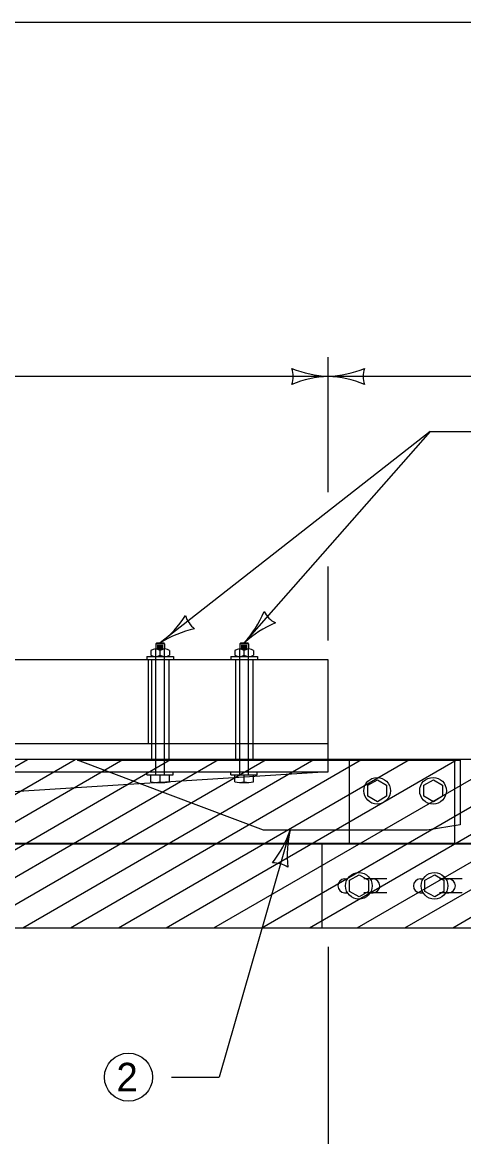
# Model space of a CAD drawing. Extents: x 49983 to 50021, y 49963.5 to 50011.4.
# Drawn here: x 50004.438 to 50005.363, y 49996.667 to 49998.999 of the extents above; entities that cross this region are included whole.
import ezdxf

# ---------------------------------------------------------------- set-up
doc = ezdxf.new("R2010")
doc.units = 0
for name, color, linetype in [('Level 1', 7, 'Continuous'), ('Level 10', 7, 'Continuous'), ('Level 2', 7, 'Continuous'), ('Level 3', 7, 'Continuous'), ('Level 4', 7, 'Continuous')]:
    doc.layers.add(name, color=color, linetype=linetype)

msp = doc.modelspace()

# ---------------------------------------------------------------- linework, layer by layer
at = {"layer": 'Level 1'}
for p, q in [((50004.7181, 49997.6984), (50004.7199, 49997.7002)), ((50004.7181, 49997.6984), (50004.7181, 49997.6876)), ((50004.7363, 49997.6984), (50004.7181, 49997.6984)), ((50004.7199, 49997.7002), (50004.7345, 49997.7002)), ((50004.7207, 49997.6956), (50004.7336, 49997.6956)), ((50004.7363, 49997.6984), (50004.7345, 49997.7002)), ((50004.7363, 49997.6984), (50004.7363, 49997.6876)), ((50004.8939, 49997.6984), (50004.8957, 49997.7002)), ((50004.8939, 49997.6984), (50004.8939, 49997.6876)), ((50004.9122, 49997.6984), (50004.8939, 49997.6984)), ((50004.8957, 49997.7002), (50004.9104, 49997.7002)), ((50004.8966, 49997.6956), (50004.9094, 49997.6956)), ((50004.9122, 49997.6984), (50004.9104, 49997.7002)), ((50004.9122, 49997.6984), (50004.9122, 49997.6876)), ((50004.6991, 49997.6717), (50004.7549, 49997.6717)), ((50004.6991, 49997.6717), (50004.6991, 49997.6651)), ((50004.7075, 49997.6846), (50004.7075, 49997.6747)), ((50004.7174, 49997.6876), (50004.737, 49997.6876)), ((50004.7207, 49997.6938), (50004.7336, 49997.6938)), ((50004.7207, 49997.692), (50004.7336, 49997.692)), ((50004.7207, 49997.6901), (50004.7336, 49997.6901)), ((50004.7272, 49997.6747), (50004.7272, 49997.6846)), ((50004.7469, 49997.6846), (50004.7469, 49997.6747)), ((50004.7549, 49997.6717), (50004.7549, 49997.6651)), ((50004.8749, 49997.6717), (50004.9308, 49997.6717)), ((50004.8749, 49997.6717), (50004.8749, 49997.6651)), ((50004.8834, 49997.6846), (50004.8834, 49997.6747)), ((50004.8932, 49997.6876), (50004.9129, 49997.6876)), ((50004.8966, 49997.6938), (50004.9094, 49997.6938)), ((50004.8966, 49997.692), (50004.9094, 49997.692)), ((50004.8966, 49997.6901), (50004.9094, 49997.6901)), ((50004.9031, 49997.6747), (50004.9031, 49997.6846)), ((50004.9227, 49997.6846), (50004.9227, 49997.6747)), ((50004.9308, 49997.6717), (50004.9308, 49997.6651)), ((50005.0789, 49997.6651), (50000.7665, 49997.6651)), ((50004.7024, 49997.4894), (50004.7024, 49997.6651)), ((50005.0789, 49997.456), (50005.0789, 49997.6651)), ((50005.0789, 49997.4894), (50002.1382, 49997.4894)), ((50006.3204, 49997.456), (50003.275, 49997.456)), ((50003.8396, 49997.1042), (50004.4489, 49997.456)), ((50003.9396, 49997.1042), (50004.5489, 49997.456)), ((50004.0396, 49997.1042), (50004.6489, 49997.456)), ((50004.1396, 49997.1042), (50004.7489, 49997.456)), ((50004.2396, 49997.1042), (50004.8489, 49997.456)), ((50004.3396, 49997.1042), (50004.9489, 49997.456)), ((50004.4396, 49997.1042), (50005.0489, 49997.456)), ((50004.5396, 49997.1042), (50005.1489, 49997.456)), ((50004.6396, 49997.1042), (50005.2489, 49997.456)), ((50004.7396, 49997.1042), (50005.3489, 49997.456)), ((50004.8396, 49997.1042), (50005.4489, 49997.456)), ((50004.9396, 49997.1042), (50005.5489, 49997.456)), ((50005.0396, 49997.1042), (50005.6489, 49997.456)), ((50009.122, 49997.456), (50005.1235, 49997.456)), ((50005.1396, 49997.1042), (50005.7489, 49997.456)), ((50005.2396, 49997.1042), (50005.8489, 49997.456)), ((50005.3396, 49997.1042), (50005.9489, 49997.456)), ((50003.2457, 49997.2799), (50005.4468, 49997.2799)), ((50006.3204, 49997.2803), (50003.275, 49997.2803)), ((50009.1498, 49997.2803), (50005.1235, 49997.2803)), ((50005.1133, 49997.2066), (50005.1196, 49997.2066)), ((50005.1236, 49997.2037), (50005.1438, 49997.215)), ((50005.1438, 49997.215), (50005.1635, 49997.2037)), ((50005.167, 49997.2066), (50005.1732, 49997.2066)), ((50005.2714, 49997.2066), (50005.2777, 49997.2066)), ((50005.2815, 49997.2037), (50005.3021, 49997.215)), ((50005.3021, 49997.215), (50005.3213, 49997.2037)), ((50005.3251, 49997.2066), (50005.3313, 49997.2066)), ((50005.1236, 49997.1803), (50005.1236, 49997.2037)), ((50005.1635, 49997.2037), (50005.1635, 49997.1803)), ((50005.2815, 49997.1803), (50005.2815, 49997.2037)), ((50005.3213, 49997.2037), (50005.3213, 49997.1803)), ((50005.1131, 49997.1773), (50005.1194, 49997.1773)), ((50005.1438, 49997.1691), (50005.1236, 49997.1803)), ((50005.1635, 49997.1803), (50005.1438, 49997.1691)), ((50005.167, 49997.1773), (50005.1733, 49997.1773)), ((50005.2713, 49997.1773), (50005.2776, 49997.1773)), ((50005.3021, 49997.1691), (50005.2815, 49997.1803)), ((50005.3213, 49997.1803), (50005.3021, 49997.1691)), ((50005.3251, 49997.1773), (50005.3314, 49997.1773)), ((50003.2457, 49997.1042), (50005.4468, 49997.1042))]:
    msp.add_line(p, q, dxfattribs=at)
msp.add_lwpolyline([(49999.3835, 49998.9992), (50016.7501, 49998.9992), (50016.7501, 49987.7988), (49999.3835, 49987.7988)], close=True, dxfattribs=at)
msp.add_lwpolyline([(50006.7444, 49997.2799), (50006.3204, 49997.2799), (50006.3204, 49997.456), (50003.275, 49997.456), (50003.275, 49997.2799), (50003.2457, 49997.2799), (50002.2562, 49997.4473), (50002.2558, 49997.4447), (50002.2559, 49997.452), (50001.5623, 49997.4576), (50001.5622, 49997.4503), (50001.7737, 49997.3496), (50002.2274, 49997.2739), (50003.2457, 49997.1042), (50005.4468, 49997.1042), (50005.4633, 49997.1042), (50015.1856, 49997.1042), (50015.1855, 49997.1666), (50015.1344, 49997.1847), (50015.2365, 49997.2209), (50015.1855, 49997.239), (50015.1855, 49997.2799), (50012.5423, 49997.2799)], dxfattribs=at)
for centre in [(50005.1432, 49997.1919), (50005.3014, 49997.1919)]:
    msp.add_circle(centre, 0.0279, dxfattribs=at)
for centre, radius, start, end in [((50004.7174, 49997.6702), 0.0174, 55.616, 124.384), ((50004.7174, 49997.6891), 0.0174, 235.616, 304.384), ((50004.737, 49997.6702), 0.0174, 55.616, 124.384), ((50004.737, 49997.6891), 0.0174, 235.616, 304.384), ((50004.8932, 49997.6702), 0.0174, 55.616, 124.384), ((50004.8932, 49997.6891), 0.0174, 235.616, 304.384), ((50004.9129, 49997.6702), 0.0174, 55.616, 124.384), ((50004.9129, 49997.6891), 0.0174, 235.616, 304.384), ((50005.1139, 49997.1919), 0.0146, 92.5686, 266.9422), ((50005.1725, 49997.1919), 0.0146, 273.0578, 87.4314), ((50005.272, 49997.1919), 0.0146, 92.5686, 266.9422), ((50005.3306, 49997.1919), 0.0146, 273.0578, 87.4314)]:
    msp.add_arc(centre, radius, start, end, dxfattribs=at)
at = {"layer": 'Level 10'}
for p, q in [((50005.344, 49997.2803), (50005.344, 49997.456)), ((50005.2014, 49997.2066), (50005.1539, 49997.2066)), ((50005.3596, 49997.2066), (50005.312, 49997.2066)), ((50005.2014, 49997.1773), (50005.1539, 49997.1773)), ((50005.3596, 49997.1773), (50005.312, 49997.1773))]:
    msp.add_line(p, q, dxfattribs=at)
at = {"layer": 'Level 2'}
msp.add_circle((50004.6607, 49996.7915), 0.0503, dxfattribs=at)
at = {"layer": 'Level 3'}
for p, q in [((50005.0789, 49998.0156), (50005.0789, 49998.2981)), ((50005.0789, 49998.2581), (50000.7665, 49998.2581)), ((50013.5096, 49998.2581), (50005.0789, 49998.2581)), ((50005.2926, 49998.1429), (50004.7272, 49997.7002)), ((50005.2926, 49998.1429), (50004.9031, 49997.7002)), ((50005.2926, 49998.1429), (50005.3926, 49998.1429)), ((50005.0789, 49997.7051), (50005.0789, 49997.8601)), ((50004.9992, 49997.3085), (50004.8509, 49996.7915)), ((50005.0789, 49997.0642), (50005.0789, 49995.3262)), ((50004.7509, 49996.7915), (50004.8509, 49996.7915))]:
    msp.add_line(p, q, dxfattribs=at)
for centre, radius, start, end in [((50005.0881, 49998.4802), 0.2223, 247.456, 267.6395), ((50004.9507, 49998.2581), 0.0548, 342.1388, 17.8612), ((50005.0904, 49998.0254), 0.233, 92.8273, 112.0772), ((50005.0674, 49998.4908), 0.233, 272.8273, 292.0772), ((50005.0697, 49998.0359), 0.2223, 67.456, 87.6395), ((50005.2071, 49998.2581), 0.0548, 162.1388, 197.8612), ((50004.7296, 49997.8558), 0.233, 318.1097, 337.3596), ((50004.9933, 49997.7913), 0.0548, 207.4212, 243.1436), ((50004.5849, 49997.8847), 0.233, 307.6426, 326.8925), ((50004.8325, 49997.7734), 0.0548, 196.9541, 232.6765), ((50005.0545, 49997.5374), 0.2223, 112.7384, 132.9219), ((50004.8465, 49997.5126), 0.2223, 102.2713, 122.4548), ((50004.7882, 49997.3786), 0.2223, 321.4574, 341.641), ((50005.226, 49997.2554), 0.233, 166.8287, 186.0786), ((50004.9638, 49997.1853), 0.0548, 56.1403, 91.8626)]:
    msp.add_arc(centre, radius, start, end, dxfattribs=at)
at = {"layer": 'Level 4'}
for p, q in [((50004.7181, 49997.4242), (50004.7181, 49997.6876)), ((50004.7363, 49997.4242), (50004.7363, 49997.6876)), ((50004.8939, 49997.4243), (50004.8939, 49997.6876)), ((50004.9122, 49997.4243), (50004.9122, 49997.6876)), ((50004.709, 49997.6651), (50004.709, 49997.456)), ((50004.7454, 49997.6651), (50004.7454, 49997.456)), ((50004.8848, 49997.6651), (50004.8848, 49997.456)), ((50004.9213, 49997.6651), (50004.9213, 49997.456)), ((50005.0789, 49997.4308), (50005.0789, 49997.456)), ((50005.1229, 49997.456), (50005.1229, 49997.2803)), ((50003.275, 49997.4308), (50005.0789, 49997.4308)), ((50005.0789, 49997.4308), (50003.275, 49997.3161)), ((50004.6991, 49997.4242), (50004.6991, 49997.4308)), ((50004.6991, 49997.4242), (50004.7546, 49997.4242)), ((50004.7075, 49997.4096), (50004.7075, 49997.4242)), ((50004.727, 49997.4096), (50004.727, 49997.4242)), ((50004.7466, 49997.4096), (50004.7466, 49997.4242)), ((50004.7546, 49997.4242), (50004.7546, 49997.4308)), ((50004.8749, 49997.4243), (50004.8749, 49997.4308)), ((50004.8749, 49997.4243), (50004.9304, 49997.4243)), ((50004.8833, 49997.4096), (50004.8833, 49997.4243)), ((50004.9029, 49997.4096), (50004.9029, 49997.4243)), ((50004.9029, 49997.4083), (50004.9029, 49997.4242)), ((50004.9224, 49997.4096), (50004.9224, 49997.4243)), ((50004.9304, 49997.4243), (50004.9304, 49997.4308)), ((50004.7172, 49997.4084), (50004.7368, 49997.4084)), ((50004.8931, 49997.4085), (50004.9126, 49997.4085)), ((50005.1619, 49997.4027), (50005.1821, 49997.4139)), ((50005.1619, 49997.3793), (50005.1619, 49997.4027)), ((50005.1821, 49997.4139), (50005.2013, 49997.4027)), ((50005.2013, 49997.4027), (50005.2013, 49997.3793)), ((50005.279, 49997.4027), (50005.2992, 49997.4139)), ((50005.279, 49997.3793), (50005.279, 49997.4027)), ((50005.2992, 49997.4139), (50005.3184, 49997.4027)), ((50005.3184, 49997.4027), (50005.3184, 49997.3793)), ((50005.1821, 49997.368), (50005.1619, 49997.3793)), ((50005.2013, 49997.3793), (50005.1821, 49997.368)), ((50005.2992, 49997.368), (50005.279, 49997.3793)), ((50005.3184, 49997.3793), (50005.2992, 49997.368)), ((50005.0655, 49997.2799), (50005.0655, 49997.1042))]:
    msp.add_line(p, q, dxfattribs=at)
msp.add_lwpolyline([(50005.3555, 49997.455), (50005.3555, 49997.3195), (50005.286, 49997.3085), (50004.9437, 49997.3085), (50004.5539, 49997.455)], close=True, dxfattribs=at)
for centre in [(50005.1814, 49997.3909), (50005.2985, 49997.3909)]:
    msp.add_circle(centre, 0.0279, dxfattribs=at)
for centre in [(50004.7172, 49997.4495), (50004.7368, 49997.4495), (50004.8931, 49997.4495), (50004.9126, 49997.4495)]:
    msp.add_arc(centre, 0.0411, 256.2307, 283.7693, dxfattribs=at)

# ---------------------------------------------------------------- texts
at = {"layer": 'Level 2'}
msp.add_text('2', height=0.06, dxfattribs=at).set_placement((50004.6355, 49996.7615))

doc.saveas('drawing.dxf')
